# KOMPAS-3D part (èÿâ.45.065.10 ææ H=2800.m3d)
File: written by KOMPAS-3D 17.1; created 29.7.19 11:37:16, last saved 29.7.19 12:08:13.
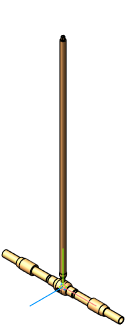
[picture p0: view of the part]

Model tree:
1. Операция без истории:1  (labels: Сталь 20  ГОСТ 1050-2013)

Referenced files in C:\Users\kka\KOMPAS_Work\Модели кранов для исследований\DN80\С удлинением\: КШГ.45.065.10 СС.a3d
